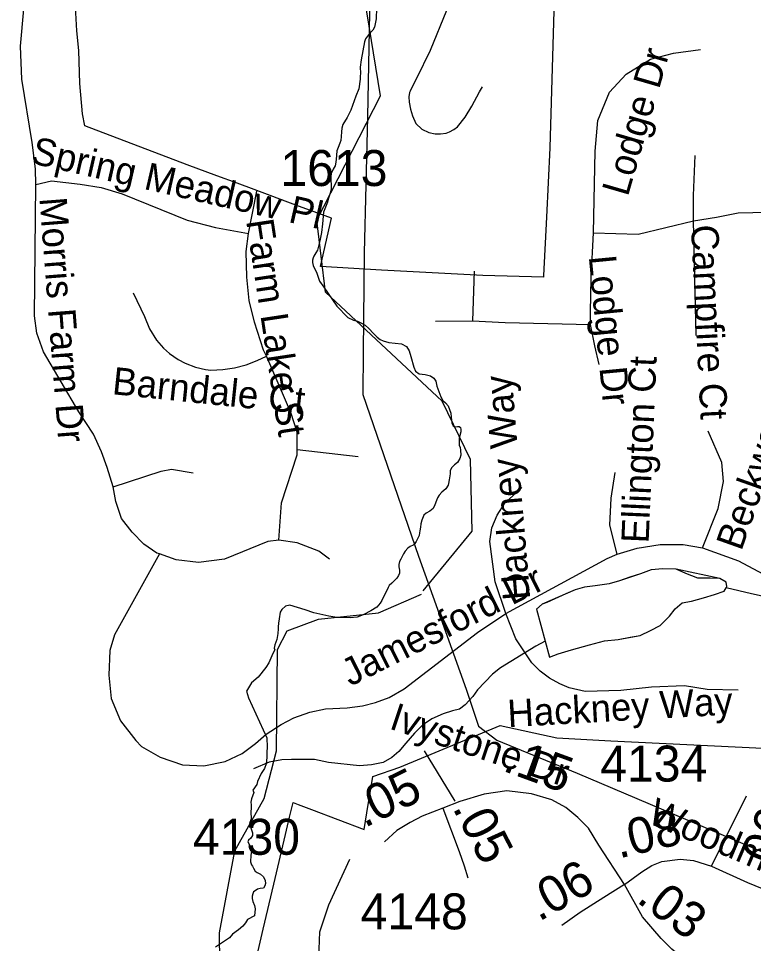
# Model space of a CAD drawing. Extents: x 1662474 to 1856135, y 779280 to 917889.
# Drawn here: x 1721963 to 1724517, y 831213 to 834427 of the extents above; entities that cross this region are included whole.
import ezdxf

# ---------------------------------------------------------------- set-up
doc = ezdxf.new("R2010")
doc.units = 0
for name, color, linetype in [('Exist Boundary Political City Limit New', 7, 'Continuous'), ('Exist Hydrographic Creek Single Shore', 7, 'Continuous'), ('Exist Hydrographic Misc Water Feature', 7, 'Continuous'), ('Exist Road Non-System Type 51', 7, 'Continuous'), ('Exist Road Non-System Type 51 Label', 7, 'Continuous'), ('Exist Road Secondary Mileage Tenths English Label', 7, 'Continuous'), ('Exist Road Secondary Type 51 Attributed', 7, 'Continuous'), ('Exist Road Secondary Type 51 Label', 7, 'Continuous'), ('Exist Road Secondary Type 51 Number Label', 7, 'Continuous'), ('Exist Utilities Electrical Transmission Line', 7, 'Continuous'), ('Map Preparation Boundary City Limit Buffer Line', 7, 'Continuous')]:
    doc.layers.add(name, color=color, linetype=linetype)

msp = doc.modelspace()

# ---------------------------------------------------------------- linework, layer by layer
at = {"layer": 'Exist Boundary Political City Limit New'}
for points in [[(1723824.5, 834494.9), (1723809.1, 833977.5), (1723797.4, 833737.2), (1723787.1, 833534.4), (1723786.9, 833529), (1723576.1, 833534.5), (1723223.9, 833552.5), (1723012.1, 833566.1), (1723050.6, 833733.9), (1722927.1, 833779.1), (1722781.8, 833832.9), (1722722.5, 833854.9), (1722652.1, 833880.9), (1722548.9, 833919.3), (1722193.4, 834054.1), (1722185.1, 834095.9), (1722176, 834201.7), (1722172, 834316.5), (1722165.9, 834384.5), (1722160.9, 834468.2)], [(1722765.6, 831057.4), (1722813.1, 831263), (1722850, 831419.6), (1722890.8, 831592.3), (1722905, 831652.4), (1722917, 831703.2), (1722917.6, 831703.1), (1722934.6, 831696.6), (1722981.6, 831679), (1723164, 831609.5), (1723173.5, 831667.5), (1723194.4, 831794.1), (1723288, 831825.6), (1723636.5, 831970.3), (1723833.2, 831927.6), (1724020.8, 831917.3), (1724646, 831887.5), (1724794.4, 831467.4), (1724795.4, 831467.4), (1724870, 831460.9), (1725190.4, 831433.2)]]:
    msp.add_lwpolyline(points, dxfattribs=at)
at = {"layer": 'Exist Hydrographic Creek Single Shore'}
for points in [[(1723206.6, 834462.6), (1723205.4, 834425.6), (1723199.8, 834396.9), (1723194.2, 834387.2), (1723179.4, 834370.2), (1723168.6, 834356.2), (1723165.6, 834346), (1723153.6, 834284.1), (1723150.2, 834257.6), (1723151, 834237.4), (1723150.5, 834225.6), (1723149.9, 834216.6), (1723145.2, 834182.8), (1723135, 834157.3), (1723117.9, 834109), (1723105.6, 834083.3), (1723090.4, 834059.4), (1723086.4, 834046.3), (1723085.9, 834033.7), (1723084.4, 834017.2), (1723083, 834002.8), (1723079.4, 833994.1), (1723073.5, 833979.6), (1723068.6, 833967.3), (1723068, 833952.6), (1723066.8, 833937.1), (1723064.9, 833921.1), (1723063.4, 833914.8), (1723056.2, 833903.2), (1723049.4, 833888.8), (1723047.9, 833878.3), (1723048.6, 833863.6), (1723048.9, 833850.8), (1723048.9, 833833.4), (1723045.8, 833820.3), (1723038.9, 833799.3), (1723036.2, 833789.1), (1723026.9, 833766.5), (1723022.9, 833754.7), (1723018.8, 833714), (1723016.1, 833683.8), (1723010, 833654.2), (1723002.1, 833622.4), (1722996.6, 833613.2), (1722989.6, 833601.9), (1722987.2, 833595.6), (1722985.1, 833588.1), (1722984.9, 833579.9), (1722987.2, 833569.4), (1722999.2, 833542.4), (1723009, 833514.8), (1723024.2, 833494.1), (1723069.4, 833427.9), (1723107.6, 833388.8), (1723126.6, 833379.1), (1723141.2, 833375.2), (1723152.9, 833370.2), (1723167.5, 833362.1), (1723180.6, 833350.2), (1723196.4, 833332.9), (1723209.5, 833320.1), (1723220, 833311.7), (1723229.8, 833307.2), (1723249.6, 833301.4), (1723293.5, 833296.4), (1723311.4, 833287.5), (1723321, 833272.3), (1723325.8, 833253.1), (1723336.5, 833215.3), (1723342.4, 833202.2), (1723355.5, 833192.2), (1723375.9, 833190.4), (1723394.8, 833185.4), (1723405.9, 833177.3), (1723412.9, 833166.8), (1723417.1, 833150.2), (1723430.2, 833112.2), (1723437.4, 833099.9), (1723447, 833091.4), (1723456.2, 833080.9), (1723460.8, 833068.6), (1723465.4, 833055.5)], [(1723465.4, 833055.5), (1723466.2, 833041.6), (1723469.1, 833022.4), (1723473.2, 833012.2), (1723476.4, 833009.8), (1723481.4, 833008.8), (1723488.2, 833009.3), (1723494.5, 833010.1), (1723499.2, 833006.7), (1723500.6, 832999.1), (1723499.8, 832991.4), (1723497.8, 832982.6), (1723494, 832968.4), (1723494.5, 832955.2), (1723494.8, 832944.5), (1723497.8, 832936.6), (1723499.5, 832927.7), (1723500.6, 832909.8), (1723496.4, 832898.8), (1723488.2, 832884.9), (1723477.5, 832876), (1723468.2, 832865.8), (1723462.5, 832856.1), (1723463.4, 832844.8), (1723460.1, 832824), (1723457.5, 832811.4), (1723456, 832805.6), (1723447.6, 832792.8), (1723433.9, 832781.8), (1723424.5, 832771.2), (1723419, 832761.6), (1723415, 832752.1), (1723410.2, 832737.9), (1723404, 832724.6), (1723391.9, 832715.1), (1723379.6, 832708), (1723371.2, 832701.7), (1723364.6, 832684.4), (1723361.5, 832671.2), (1723359.9, 832659.4), (1723357.8, 832647.4), (1723356.5, 832640.6), (1723355.1, 832631.1), (1723352.2, 832623.5), (1723349.6, 832618.8), (1723345, 832610.4), (1723339.8, 832603.6), (1723334.1, 832597.8), (1723324.2, 832592.2), (1723316.4, 832587), (1723306.1, 832576.2), (1723300.9, 832567.3), (1723295.6, 832555.8), (1723291.6, 832548.7), (1723287.5, 832540.6), (1723285.1, 832529.8), (1723284.9, 832522.2), (1723286.6, 832510.1), (1723287, 832499.6), (1723283.8, 832491.5), (1723277.8, 832483.1), (1723260.1, 832465.2), (1723251.5, 832456.8), (1723247.6, 832450), (1723241.5, 832437.4), (1723232.9, 832420.6), (1723225, 832405.4), (1723220.2, 832396.4), (1723208, 832381.5), (1723187.8, 832369.4), (1723161.2, 832355), (1723139.8, 832347.4), (1723115.2, 832345), (1723093.5, 832346.3), (1723069.4, 832346.3), (1723041, 832350.8), (1722989.6, 832362.6), (1722959.6, 832373.1), (1722906.1, 832389.1), (1722891.1, 832385.2), (1722878, 832374.1), (1722872.5, 832364.7), (1722869.1, 832341.9), (1722866.8, 832325.9), (1722865.4, 832313.8), (1722865.1, 832306.4), (1722863.6, 832290.4), (1722861.2, 832269.4), (1722853.9, 832251.1), (1722851.2, 832239.8), (1722853.9, 832234.2), (1722846.8, 832220.4), (1722832.4, 832188.1), (1722822.1, 832171.8), (1722796.1, 832138.8), (1722773, 832118.8), (1722754.9, 832089.9), (1722762.5, 832067.3), (1722826.4, 831927.9), (1722827.1, 831895.2)], [(1722827.1, 831895.2), (1722826.4, 831878.4), (1722826.4, 831859.8), (1722823.4, 831837.9), (1722817.9, 831820.9)], [(1722817.9, 831820.9), (1722806.6, 831804.4), (1722793.2, 831776.8), (1722790.6, 831765.8), (1722777.5, 831746.1), (1722781.1, 831738.2), (1722773, 831715.9), (1722770.1, 831704.9), (1722771.5, 831695.7), (1722772, 831684.1), (1722770.6, 831671), (1722771, 831646.4), (1722765.4, 831630.6), (1722769.9, 831615.1), (1722775.6, 831597.8), (1722775.9, 831588.1), (1722769.9, 831579.4), (1722761.8, 831572.6), (1722760.1, 831566.3), (1722766, 831556.3), (1722769.6, 831545.6), (1722772.8, 831532.9), (1722770.6, 831520.1), (1722768.9, 831496.8), (1722772.2, 831486.5), (1722776.5, 831481.8), (1722779.6, 831474.7), (1722785.1, 831465.2), (1722792.5, 831459.5), (1722803.5, 831454.2), (1722814, 831445.1), (1722820, 831432.2), (1722820.8, 831421.7), (1722819, 831413.2), (1722814.2, 831405.7), (1722802.4, 831404.4), (1722793.5, 831401.8), (1722784.9, 831396.8), (1722780.1, 831392.6), (1722777.5, 831385.8), (1722774.6, 831377.3), (1722774.6, 831369.7), (1722777.8, 831359.8), (1722783.2, 831345.1), (1722784.9, 831334.2), (1722782.8, 831309.3), (1722758.9, 831297), (1722752.2, 831284.9), (1722742.4, 831273.1), (1722726.9, 831260.5), (1722706.1, 831245.3), (1722696.6, 831233.5), (1722647.4, 831200.2)]]:
    msp.add_lwpolyline(points, dxfattribs=at)
at = {"layer": 'Exist Hydrographic Misc Water Feature'}
for points in [[(1723220.4, 834158.6), (1723165.4, 834501.1), (1722908.3, 834736.1), (1722868.3, 834871.5), (1722872.4, 835252.2), (1722906.5, 835386.1), (1723193.3, 835777.4), (1723521.4, 836007), (1723554.4, 836072), (1723557.3, 836321.4), (1723582.3, 836373.4), (1723801.3, 836529.8), (1723802.3, 836638.1), (1723561.4, 836807.1), (1723520.4, 836880.1), (1723514.4, 837041.2), (1723716.4, 837329.2), (1723895.4, 837670.2), (1723988.3, 837793), (1724323.4, 837966.7), (1724415.4, 838056.7), (1724610.4, 838371.2)], [(1723368.8, 832438.2), (1723539.4, 832645.5), (1723533.3, 832895.1), (1723435.3, 833097.2), (1723030.3, 833476.4), (1722999.3, 833726.5), (1723220.4, 834158.6)], [(1724421.6, 832449.4), (1724424, 832454.3), (1724422, 832468.3), (1724400.1, 832481.9), (1724366.2, 832482.5), (1724324.2, 832482.5), (1724282.1, 832499.1), (1724248.1, 832514.5), (1724202.2, 832514.6), (1724162, 832511.3), (1724124.1, 832497.3), (1724087.8, 832485.7), (1724051.7, 832473.4), (1724015.6, 832463.4), (1723967.4, 832456.2), (1723929.7, 832452), (1723897.5, 832442), (1723865.3, 832428), (1723827.3, 832410.6), (1723799, 832398.1), (1723783.1, 832392.7), (1723763.6, 832375), (1723793.5, 832264.4)], [(1724421.6, 832449.4), (1724424, 832454.3), (1724422, 832468.3), (1724400.1, 832481.9), (1724248.1, 832514.5), (1724202.2, 832514.6), (1724162, 832511.3), (1724124.1, 832497.3), (1724051.7, 832473.4), (1724015.6, 832463.4), (1723967.4, 832456.2), (1723929.7, 832452), (1723897.5, 832442), (1723783.1, 832392.7), (1723763.6, 832375), (1723793.5, 832264.4)], [(1722670.8, 830409.9), (1722661.8, 831250.4), (1722714.9, 831534.9), (1722816.8, 831716.6), (1722859.8, 831883.1), (1722862.7, 832234.3), (1722896.7, 832299.3), (1723005.8, 832339.7), (1723213.8, 832361.7), (1723363.2, 832427)], [(1723793.5, 832264.4), (1723808.5, 832208.3), (1723838.2, 832220), (1723884.6, 832233.9), (1723946.7, 832251.5), (1723999, 832265.2), (1724047, 832269.1), (1724089, 832277.3), (1724123.2, 832283.2), (1724159.1, 832301.3), (1724193.2, 832318.7), (1724225.3, 832350.9), (1724245.4, 832376.7), (1724269.6, 832396.7), (1724301.8, 832402.6), (1724343.9, 832414.1), (1724381.8, 832426.4), (1724415.8, 832438), (1724421.6, 832449.4)], [(1723793.5, 832264.4), (1723808.5, 832208.3), (1723838.2, 832220), (1723884.6, 832233.9), (1723946.7, 832251.5), (1723999, 832265.2), (1724047, 832269.1), (1724123.2, 832283.2), (1724159.1, 832301.3), (1724193.2, 832318.7), (1724225.3, 832350.9), (1724245.4, 832376.7), (1724269.6, 832396.7), (1724301.8, 832402.6), (1724343.9, 832414.1), (1724381.8, 832426.4), (1724415.8, 832438), (1724421.6, 832449.4)], [(1725126.1, 831542.3), (1725071.2, 831623), (1725041.5, 831658.9), (1725005.4, 831699), (1724963.7, 831735.1), (1724927.7, 831765.4), (1724885.8, 831805.7), (1724857.9, 831849.7), (1724830.3, 831910.1), (1724808.3, 831962.3), (1724786.6, 832008.7), (1724770.6, 832034.5), (1724739, 832080.2), (1724659.4, 832267.3), (1724641.8, 832316.9), (1724616.2, 832375.7), (1724592, 832403.3), (1724558.1, 832417.9), (1724510, 832428), (1724421.6, 832449.4)], [(1723793.5, 832264.4), (1723760.5, 832246.2), (1723638.1, 832170.8), (1723610, 832149.2), (1723557.7, 832095.3), (1723541.3, 832071), (1723515.3, 832042.8), (1723495.2, 832027.6), (1723471.2, 832021.5), (1723439, 832011.5), (1723398.8, 831993.5), (1723366.8, 831972), (1723338.7, 831943.8), (1723308.6, 831910), (1723284.2, 831880.1), (1723260, 831860.1), (1723230.2, 831841.8), (1723190, 831834.4), (1723147.8, 831830.4), (1723039.7, 831842.4), (1722991.8, 831853.2), (1722911.8, 831853.2), (1722877.7, 831851.4), (1722833.7, 831843.3), (1722779.3, 831820.6)]]:
    msp.add_lwpolyline(points, dxfattribs=at)
at = {"layer": 'Exist Road Non-System Type 51'}
for p, q in [((1722762, 833680.7), (1722791.4, 833827.4)), ((1724317.9, 833325.6), (1724308.6, 833723.8)), ((1723546, 833549.2), (1723540.8, 833377)), ((1723411.6, 833376.2), (1723540.8, 833377)), ((1722931.6, 832929.2), (1723143.6, 832905.9))]:
    msp.add_line(p, q, dxfattribs=at)
for points in [[(1722023.6, 833850.5), (1722021.9, 833904.6), (1722010.1, 833996.4), (1721974.6, 834216.4), (1721969.4, 834331.1), (1721993.2, 834589.6), (1721981.4, 834650.2), (1721962.9, 834694.4)], [(1723960.6, 833682), (1723967, 833966.2), (1723976.1, 834072.5), (1724016.9, 834171.5), (1724074.1, 834233.9), (1724159.6, 834285.9), (1724238.9, 834306.7), (1724332.6, 834319.7)], [(1724308.6, 833723.8), (1724308.6, 833812.2), (1724314.8, 833951.8)], [(1722291.4, 832800.4), (1722271.4, 832867.6), (1722251, 832922.2), (1722223.6, 832983.6), (1722173, 833061.2), (1722049.4, 833268.9), (1722026.4, 833334.5), (1722018.6, 833394.4), (1722023.6, 833850.5)], [(1722023.6, 833850.5), (1722077, 833863.4), (1722177, 833852.1), (1722249.9, 833840.2), (1722322.6, 833818.4), (1722548.6, 833726.4), (1722647.6, 833701.4), (1722762, 833680.7)], [(1724308.6, 833723.8), (1724388.8, 833737.1), (1724463.9, 833751.5), (1724667.4, 833756.2)], [(1723960.6, 833682), (1724116.6, 833677.8), (1724308.6, 833723.8)], [(1722824.8, 833254.4), (1722814.8, 833274.7), (1722782.5, 833372.5), (1722764.6, 833446.9), (1722756.2, 833528.4), (1722754.6, 833618.2), (1722762, 833680.7)], [(1723951.2, 833363.9), (1723951.2, 833406.9), (1723953.4, 833525.6), (1723960.6, 833682)], [(1722361.2, 833474.4), (1722400.6, 833391.4), (1722417.6, 833348.7), (1722442.6, 833309.6), (1722467.2, 833282), (1722487.9, 833263.6), (1722518.1, 833242.4), (1722542.6, 833229.2), (1722577.5, 833216.1), (1722613.1, 833208), (1722631.6, 833205.6), (1722672.8, 833208), (1722714, 833213.8), (1722753.9, 833224.2), (1722791.9, 833238.7), (1722824.8, 833254.4)], [(1723540.8, 833377), (1723654, 833370.7), (1723951.2, 833363.9)], [(1723981.4, 833224.8), (1723965.9, 833289.4), (1723951.2, 833363.9)], [(1722931.6, 832929.2), (1722931.6, 832990.4), (1722909.2, 833058.1), (1722824.8, 833254.4)], [(1724339.9, 832588.4), (1724394, 832725.2), (1724412.4, 832818.2), (1724407.4, 832884.9), (1724359.4, 832993.4)], [(1722867.9, 832614.9), (1722876.9, 832744.7), (1722931.6, 832910.9), (1722931.6, 832929.2)], [(1722291.4, 832800.4), (1722458.9, 832855), (1722494.2, 832861.5), (1722569.9, 832848.9)], [(1724043.9, 832566), (1724017.4, 832667), (1724022.4, 832760.2), (1724036, 832850.2)], [(1722453.1, 832566.8), (1722444.1, 832569.4), (1722398.8, 832601.2), (1722358.1, 832642.1), (1722321.4, 832689.9), (1722301.1, 832748.9), (1722291.4, 832800.4)], [(1723655.9, 832359.9), (1723618.9, 832470.4), (1723600.6, 832610.4), (1723607.6, 832657.1), (1723626, 832701.9), (1723652.5, 832743.7), (1723711.6, 832797.8)], [(1722867.9, 832614.9), (1722829.1, 832610.4), (1722679.1, 832548.9), (1722588.2, 832537.4), (1722510.4, 832546.6), (1722453.1, 832566.8)], [(1723043.4, 832549.2), (1723006.9, 832576.5), (1722931.6, 832605.4), (1722867.9, 832614.9)], [(1724043.9, 832566), (1724113.4, 832587.5), (1724192.4, 832599.4), (1724272.5, 832599.4), (1724339.9, 832588.4)], [(1724339.9, 832588.4), (1724465.6, 832542.4), (1724584, 832478.9), (1724627.9, 832438.7)], [(1722453.1, 832566.8), (1722296.4, 832285.9), (1722280.1, 832231.1), (1722276.4, 832145.8), (1722284.6, 832064.7), (1722317.6, 831986.5), (1722370.6, 831918.5), (1722390.4, 831898.2), (1722455.4, 831860.8), (1722533.4, 831833.8), (1722606.9, 831830.6), (1722680.9, 831845.2), (1722740.2, 831873.1), (1722786.4, 831908), (1722823.9, 831940.5), (1722875.9, 831974.4), (1722920.2, 831998), (1722975.6, 832016.8), (1723030.2, 832028.2), (1723104.8, 832032.4), (1723157.9, 832038.7), (1723203.5, 832051), (1723251, 832068.1), (1723302.6, 832097.9), (1723557.8, 832293.9), (1723655.9, 832359.9)], [(1723655.9, 832359.9), (1724008.6, 832550.5), (1724043.9, 832566)], [(1724464.4, 832094.1), (1724355.9, 832095.4), (1724277.1, 832109), (1724162.2, 832103.9), (1724055.8, 832092.5), (1723932.4, 832088.9), (1723877.1, 832101.9), (1723844.4, 832115.4), (1723808.4, 832134.8), (1723776.1, 832160), (1723747.2, 832189.1), (1723691.1, 832272), (1723655.9, 832359.9)]]:
    msp.add_lwpolyline(points, dxfattribs=at)
at = {"layer": 'Exist Road Secondary Type 51 Attributed'}
msp.add_line((1724371.6, 831482.1), (1724492.6, 831725.9), dxfattribs=at)
for points in [[(1723603.1, 835505.2), (1723581.6, 834608.5), (1723581.1, 834588.8), (1723575.7, 834569.4), (1723567.1, 834554.6), (1723548.6, 834542.7), (1723511.1, 834522.8), (1723480.9, 834502.1), (1723463.7, 834480), (1723449.9, 834455), (1723393, 834316.4), (1723345.8, 834218.9), (1723331.4, 834190.2), (1723324.4, 834174.6)], [(1723324.4, 834174.6), (1723322.2, 834169.7), (1723319.1, 834155.3), (1723320.2, 834136.9), (1723325.3, 834112.2), (1723332.5, 834088.6), (1723343.8, 834063), (1723364.3, 834042.5), (1723388.9, 834031.2), (1723410.5, 834027.1), (1723429, 834026), (1723449.1, 834029.4), (1723461.2, 834033.6), (1723475.7, 834041.5), (1723488.5, 834050.7), (1723515.1, 834084.5), (1723538.8, 834122.5), (1723564.5, 834172.8), (1723575.8, 834190.2)], [(1724069, 831418.9), (1723980, 831555.1), (1723943.3, 831614.4), (1723906.6, 831651), (1723864.7, 831685.9), (1723815.8, 831712.1), (1723745.9, 831733.1), (1723659.6, 831743.8), (1723580.6, 831732.4), (1723496.5, 831706.9), (1723437.7, 831683.3)], [(1723437.7, 831683.3), (1723365.3, 831656), (1723324.5, 831634.3), (1723277.3, 831606.3), (1723235.3, 831566.8)], [(1723437.7, 831683.3), (1723494, 831532.5), (1723511.8, 831482.8), (1723524.5, 831442)], [(1723711.2, 830539.7), (1723717.1, 830640.9), (1723717.1, 830748.2), (1723710.1, 830817.5), (1723658.2, 830883.3), (1723588.9, 830931.8), (1723478, 830959.5), (1723381, 830973.3), (1723214.7, 830976.8), (1723110.7, 831004.5), (1723048.4, 831070.3), (1723006.8, 831163.8), (1723010.3, 831253.8), (1723041.4, 831347.3), (1723114.2, 831506.6)], [(1724069, 831418.9), (1724128.7, 831462.2), (1724163.9, 831483.9), (1724198.7, 831498.8), (1724262.6, 831506.9), (1724308.9, 831502), (1724371.6, 831482.1)], [(1724371.6, 831482.1), (1724496.8, 831425.6), (1724776.8, 831311.2), (1725044.6, 831199), (1725115.3, 831161), (1725164.4, 831124.8), (1725206.7, 831081.2)], [(1724069, 831418.9), (1723997.4, 831373.5), (1723915.3, 831321.2), (1723850.7, 831275.8)], [(1724324.5, 831118.4), (1724233.8, 831193.8), (1724196.2, 831230.2), (1724131.9, 831306), (1724069, 831418.9)]]:
    msp.add_lwpolyline(points, dxfattribs=at)
at = {"layer": 'Exist Road Secondary Type 51 Label'}
msp.add_lwpolyline([(1723372.5, 831883), (1723479.6, 831707.7)], dxfattribs=at)
at = {"layer": 'Exist Utilities Electrical Transmission Line'}
msp.add_lwpolyline([(1723473.3, 839431), (1723445.1, 838486.9), (1723411.2, 837570.7), (1723389.1, 836806.6), (1723380.6, 836578.5), (1723373.2, 836450.5), (1723288.7, 836219.4), (1723118.2, 835806.8), (1723048.4, 835651.6), (1723038.9, 835135.3), (1723035.3, 834803.2), (1723115.6, 834640.3), (1723184.2, 834509.4), (1723175.6, 834085.4), (1723164.6, 833613.2), (1723161, 833269.1), (1723159.4, 833121.1), (1723353.4, 832558.7), (1723518.7, 832096.9), (1723561.3, 831968.3), (1723624.9, 831919.6), (1723903.9, 831804.7), (1725017.8, 831332.8), (1725532.2, 831119.2)], dxfattribs=at)
at = {"layer": 'Map Preparation Boundary City Limit Buffer Line'}
for points in [[(1723824.5, 834494.9), (1723809.1, 833977.5), (1723797.4, 833737.2), (1723787.1, 833534.4), (1723786.9, 833529), (1723576.1, 833534.5), (1723223.9, 833552.5), (1723012.1, 833566.1), (1723050.6, 833733.9), (1722927.1, 833779.1), (1722781.8, 833832.9), (1722722.5, 833854.9), (1722652.1, 833880.9), (1722548.9, 833919.3), (1722193.4, 834054.1), (1722185.1, 834095.9), (1722176, 834201.7), (1722172, 834316.5), (1722165.9, 834384.5), (1722160.9, 834468.2)], [(1722765.6, 831057.4), (1722813.1, 831263), (1722850, 831419.6), (1722890.8, 831592.3), (1722905, 831652.4), (1722917, 831703.2), (1722917.6, 831703.1), (1722934.6, 831696.6), (1722981.6, 831679), (1723164, 831609.5), (1723173.5, 831667.5), (1723194.4, 831794.1), (1723288, 831825.6), (1723636.5, 831970.3), (1723833.2, 831927.6), (1724020.8, 831917.3), (1724646, 831887.5), (1724794.4, 831467.4), (1724795.4, 831467.4), (1724870, 831460.9), (1725190.4, 831433.2)]]:
    msp.add_lwpolyline(points, dxfattribs=at)

# ---------------------------------------------------------------- texts
at = {"layer": 'Exist Road Non-System Type 51 Label'}
for s, rotation, p in [('Lodge Dr', 73.8066, (1724080.2, 833805.8)), ('Spring Meadow Pl', 347.1106, (1722002.6, 833925.3)), ('Morris Farm Dr', 274.4396, (1722035.5, 833803.3)), ('Farm Lake St', 278.6108, (1722753.7, 833724.3)), ('Campfire Ct', 272.8607, (1724299.7, 833708.8)), ('Lodge Dr', 275.482, (1723944.5, 833600.6)), ('Beckworth Ct', 70.4741, (1724474.6, 832574.4)), ('Ellington Ct', 87.5119, (1724152.5, 832602.8)), ('Barndale Ct', 354.0825, (1722286, 833122.2)), ('Hackney Way', 94.7608, (1723741.7, 832409.9)), ('Jamesford Dr', 26.6633, (1723115.7, 832105.3)), ('Hackney Way', 3.2674, (1723664.7, 831964.8))]:
    msp.add_text(s, height=95, rotation=rotation, dxfattribs=at).set_placement(p)
at = {"layer": 'Exist Road Secondary Mileage Tenths English Label'}
for s, rotation, p in [('.15', 339.8745, (1723641.4, 831814.8)), ('.05', 26.1422, (1723165.1, 831614)), ('.05', 297.5211, (1723469.7, 831684.9)), ('.08', 13.2348, (1724049.5, 831508.4)), ('.06', 69.3045, (1724572.6, 831436)), ('.06', 29.2774, (1723771.2, 831288)), ('.03', 323.3657, (1724106.9, 831359.8))]:
    msp.add_text(s, height=125, rotation=rotation, dxfattribs=at).set_placement(p)
at = {"layer": 'Exist Road Secondary Type 51 Label'}
for s, rotation, p in [('Ivystone Dr', 341.5546, (1723247.5, 831961.1)), ('Woodmont Rd', 336.8731, (1724144.2, 831634.4))]:
    msp.add_text(s, height=95, rotation=rotation, dxfattribs=at).set_placement(p)
at = {"layer": 'Exist Road Secondary Type 51 Number Label'}
for s, p in [('1613', (1722873.3, 833845.2)), ('4134', (1723984.6, 831775.9)), ('4130', (1722569.3, 831521.6)), ('4148', (1723152.2, 831262.5))]:
    msp.add_text(s, height=125, dxfattribs=at).set_placement(p)

doc.saveas('drawing.dxf')
